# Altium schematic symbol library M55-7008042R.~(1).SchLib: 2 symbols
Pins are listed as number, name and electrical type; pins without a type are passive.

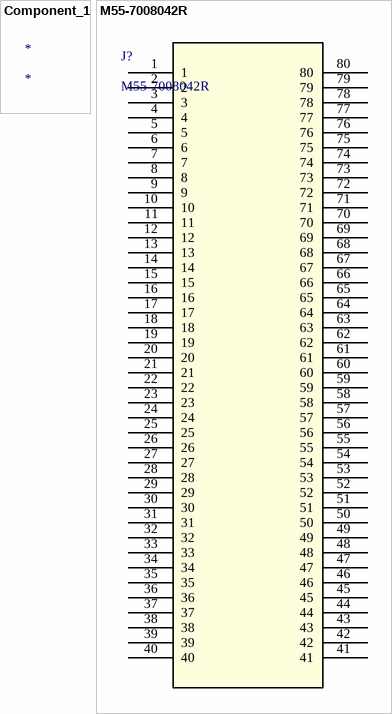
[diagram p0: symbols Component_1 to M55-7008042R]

## Component_1
designator *

## M55-7008042R
designator J?
No Description Available; Mfr_Name: Harwin
footprint M55-7008042R_HRW
pins: 1, 2, 3, 4, 5, 6, 7, 8, 9, 10, 11, 12, 13, 14, 15, 16, 17, 18, 19, 20, 21, 22, 23, 24, 25, 26, 27, 28, 29, 30, 31, 32, 33, 34, 35, 36, 37, 38, 39, 40, 41, 42, 43, 44, 45, 46, 47, 48, 49, 50, 51, 52, 53, 54, 55, 56, 57, 58, 59, 60, 61, 62, 63, 64, 65, 66, 67, 68, 69, 70, 71, 72, 73, 74, 75, 76, 77, 78, 79, 80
